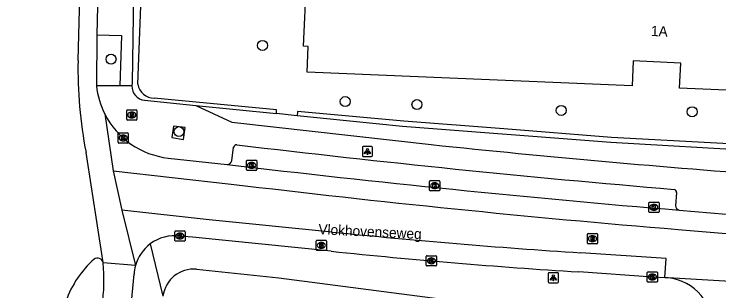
# Model space of a CAD drawing. Extents: x 161355 to 162026, y 386504 to 387459.
# Drawn here: x 161381.9 to 161450.8, y 386816.9 to 386843.9 of the extents above; entities that cross this region are included whole.
import ezdxf

# ---------------------------------------------------------------- set-up
doc = ezdxf.new("R2010")
doc.units = 0
for name, color, linetype in [('IMGEO_Boom', 7, 'Continuous'), ('IMGEO_Brandkraan', 7, 'Continuous'), ('IMGEO_Fietspad_gesloten', 7, 'Continuous'), ('IMGEO_Groenvoorziening', 7, 'Continuous'), ('IMGEO_Haag', 7, 'Continuous'), ('IMGEO_Kolk', 7, 'Continuous'), ('IMGEO_Lichtpunt', 7, 'Continuous'), ('IMGEO_Openbare_ruimte_label', 7, 'Continuous'), ('IMGEO_Pand', 7, 'Continuous'), ('IMGEO_Pand_nummerreeks', 7, 'Continuous'), ('IMGEO_Rijbaan_lokaal_gesloten', 7, 'Continuous'), ('IMGEO_Rijbaan_lokaal_open', 7, 'Continuous'), ('IMGEO_Rioolput', 7, 'Continuous'), ('IMGEO_Voetpad_open', 7, 'Continuous')]:
    doc.layers.add(name, color=color, linetype=linetype)

msp = doc.modelspace()

# ---------------------------------------------------------------- linework, layer by layer
at = {"layer": 'IMGEO_Boom'}
for centre in [(161406.16, 386840.885), (161391.344, 386839.543), (161414.259, 386835.401), (161421.273, 386835.11), (161435.387, 386834.536), (161448.192, 386834.404), (161397.993, 386832.461)]:
    msp.add_circle(centre, 0.489, dxfattribs=at)
at = {"layer": 'IMGEO_Brandkraan'}
for p, q in [((161392.882, 386833.669), (161392.882, 386834.521)), ((161392.957, 386834.595), (161393.809, 386834.595)), ((161393.37, 386834.375), (161393.395, 386834.375)), ((161393.883, 386834.521), (161393.883, 386833.669)), ((161393.809, 386833.595), (161392.957, 386833.595)), ((161393.393, 386833.815), (161393.368, 386833.815))]:
    msp.add_line(p, q, dxfattribs=at)
for points in [[(161392.882, 386833.669), (161392.882, 386834.521)], [(161392.957, 386834.595), (161393.809, 386834.595)], [(161393.23, 386834.295), (161393.23, 386833.895), (161393.443, 386833.895)], [(161393.461, 386834.295), (161393.23, 386834.295)], [(161393.883, 386834.521), (161393.883, 386833.669)], [(161393.809, 386833.595), (161392.957, 386833.595)], [(161393.409, 386834.214), (161393.355, 386834.214), (161393.355, 386834.138)], [(161393.355, 386834.138), (161393.408, 386834.138)], [(161393.417, 386834.062), (161393.355, 386834.062), (161393.355, 386833.981)], [(161393.355, 386833.981), (161393.417, 386833.981)]]:
    msp.add_lwpolyline(points, dxfattribs=at)
for centre, radius, start, end in [((161392.959, 386834.519), 0.0765, 91.55205, 178.44795), ((161392.959, 386834.519), 0.0765, 91.55205, 178.44795), ((161393.465, 386834.15), 0.145, 59.4692, 91.53667), ((161393.49, 386834.197), 0.0922, 285.51372, 58.15012), ((161393.807, 386834.519), 0.0765, 1.55205, 88.44795), ((161393.807, 386834.519), 0.0765, 1.55205, 88.44795), ((161392.959, 386833.671), 0.0765, 181.55205, 268.44795), ((161392.959, 386833.671), 0.0765, 181.55205, 268.44795), ((161393.41, 386834.176), 0.0379, 267.82845, 90.93552), ((161393.418, 386834.021), 0.0404, 269.87594, 90.50774), ((161393.449, 386834.146), 0.251, 268.66757, 293.53466), ((161393.495, 386834.005), 0.105, 301.31148, 78.98903), ((161393.807, 386833.671), 0.0765, 271.55205, 358.44795), ((161393.807, 386833.671), 0.0765, 271.55205, 358.44795)]:
    msp.add_arc(centre, radius, start, end, dxfattribs=at)
for centre, major_axis, ratio, start_param, end_param in [((161393.369, 386834.095), (-0.387, 0.002), 0.722429, 4.712389, 7.853982), ((161393.394, 386834.095), (-0.39, 0.002), 0.717154, 1.570796, 4.712389)]:
    msp.add_ellipse(centre, major_axis=major_axis, ratio=ratio, start_param=start_param, end_param=end_param, dxfattribs=at)
at = {"layer": 'IMGEO_Fietspad_gesloten'}
msp.add_lwpolyline([(161381.864, 386712.557), (161383.032, 386721.496), (161385.721, 386742.066), (161386.605, 386750), (161389.646, 386777.28), (161393.272, 386815.123), (161393.6, 386818.527)], dxfattribs=at)
for centre, radius, start, end in [((161373.711, 386817.975), 16.944, 351.43496, 5.63796), ((161397.624, 386818.31), 4.029, 164.69671, 176.90621)]:
    msp.add_arc(centre, radius, start, end, dxfattribs=at)
at = {"layer": 'IMGEO_Groenvoorziening'}
msp.add_lwpolyline([(161409.554, 386834.019), (161407.52, 386834.224)], dxfattribs=at)
at = {"layer": 'IMGEO_Haag'}
for points in [[(161393.965, 386837.094), (161395.556, 386878.648), (161396.501, 386879.764), (161425.128, 386878.71), (161433.124, 386871.146)], [(161407.52, 386834.224), (161407.534, 386834.586), (161395.561, 386835.719)], [(161399.64, 386835.019), (161407.52, 386834.224)], [(161481.019, 386829.466), (161481.006, 386830.048), (161455.439, 386831.092), (161440.307, 386831.903), (161429.776, 386832.736), (161419.975, 386833.49), (161409.586, 386834.431), (161409.554, 386834.019)], [(161481.019, 386829.466), (161454.814, 386830.559), (161440.24, 386831.401), (161419.848, 386832.981), (161409.554, 386834.019)]]:
    msp.add_lwpolyline(points, dxfattribs=at)
msp.add_arc((161395.593, 386837.37), 1.652, 189.63359, 268.87471, dxfattribs=at)
at = {"layer": 'IMGEO_Kolk'}
for p, q in [((161392.036, 386831.424), (161392.036, 386832.276)), ((161392.111, 386832.35), (161392.963, 386832.35)), ((161393.037, 386832.276), (161393.037, 386831.424)), ((161392.547, 386831.57), (161392.522, 386831.57)), ((161392.524, 386832.13), (161392.549, 386832.13)), ((161392.963, 386831.35), (161392.111, 386831.35)), ((161404.595, 386828.754), (161404.595, 386829.606)), ((161404.67, 386829.68), (161405.522, 386829.68)), ((161405.083, 386829.46), (161405.108, 386829.46)), ((161405.596, 386829.606), (161405.596, 386828.754)), ((161405.106, 386828.9), (161405.081, 386828.9)), ((161405.522, 386828.68), (161404.67, 386828.68)), ((161422.508, 386826.752), (161422.508, 386827.604)), ((161422.583, 386827.678), (161423.435, 386827.678)), ((161422.996, 386827.458), (161423.021, 386827.458)), ((161423.509, 386827.604), (161423.509, 386826.752)), ((161423.019, 386826.898), (161422.994, 386826.898)), ((161423.435, 386826.678), (161422.583, 386826.678)), ((161443.947, 386824.643), (161443.947, 386825.495)), ((161444.022, 386825.569), (161444.874, 386825.569)), ((161444.435, 386825.349), (161444.46, 386825.349)), ((161444.948, 386825.495), (161444.948, 386824.643)), ((161444.458, 386824.789), (161444.433, 386824.789)), ((161444.874, 386824.569), (161444.022, 386824.569)), ((161397.586, 386821.838), (161397.586, 386822.69)), ((161397.661, 386822.764), (161398.513, 386822.764)), ((161398.587, 386822.69), (161398.587, 386821.838)), ((161398.097, 386821.984), (161398.072, 386821.984)), ((161398.074, 386822.544), (161398.099, 386822.544)), ((161398.513, 386821.764), (161397.661, 386821.764)), ((161422.181, 386819.415), (161422.181, 386820.267)), ((161422.256, 386820.341), (161423.108, 386820.341)), ((161422.669, 386820.121), (161422.694, 386820.121)), ((161423.182, 386820.267), (161423.182, 386819.415)), ((161423.108, 386819.341), (161422.256, 386819.341)), ((161422.692, 386819.561), (161422.667, 386819.561)), ((161443.801, 386817.836), (161443.801, 386818.688)), ((161443.876, 386818.762), (161444.728, 386818.762)), ((161444.289, 386818.542), (161444.314, 386818.542)), ((161444.802, 386818.688), (161444.802, 386817.836)), ((161444.728, 386817.762), (161443.876, 386817.762)), ((161444.312, 386817.982), (161444.287, 386817.982))]:
    msp.add_line(p, q, dxfattribs=at)
for points in [[(161392.036, 386831.424), (161392.036, 386832.276)], [(161392.111, 386832.35), (161392.963, 386832.35)], [(161393.037, 386832.276), (161393.037, 386831.424)], [(161392.357, 386832.05), (161392.48, 386832.05), (161392.48, 386831.899), (161392.61, 386832.05), (161392.774, 386832.05), (161392.628, 386831.899), (161392.781, 386831.65), (161392.629, 386831.65), (161392.544, 386831.814), (161392.48, 386831.747), (161392.48, 386831.65), (161392.357, 386831.65), (161392.357, 386832.05)], [(161392.963, 386831.35), (161392.111, 386831.35)], [(161404.595, 386828.754), (161404.595, 386829.606)], [(161404.67, 386829.68), (161405.522, 386829.68)], [(161405.596, 386829.606), (161405.596, 386828.754)], [(161404.916, 386829.38), (161405.039, 386829.38), (161405.039, 386829.229), (161405.169, 386829.38), (161405.333, 386829.38), (161405.187, 386829.229), (161405.34, 386828.98), (161405.188, 386828.98), (161405.103, 386829.144), (161405.039, 386829.077), (161405.039, 386828.98), (161404.916, 386828.98), (161404.916, 386829.38)], [(161405.522, 386828.68), (161404.67, 386828.68)], [(161422.508, 386826.752), (161422.508, 386827.604)], [(161422.583, 386827.678), (161423.435, 386827.678)], [(161422.829, 386827.378), (161422.952, 386827.378), (161422.952, 386827.227), (161423.082, 386827.378), (161423.246, 386827.378), (161423.1, 386827.227), (161423.253, 386826.978), (161423.101, 386826.978), (161423.016, 386827.142), (161422.952, 386827.075), (161422.952, 386826.978), (161422.829, 386826.978), (161422.829, 386827.378)], [(161423.509, 386827.604), (161423.509, 386826.752)], [(161423.435, 386826.678), (161422.583, 386826.678)], [(161443.947, 386824.643), (161443.947, 386825.495)], [(161444.022, 386825.569), (161444.874, 386825.569)], [(161444.948, 386825.495), (161444.948, 386824.643)], [(161444.268, 386825.269), (161444.391, 386825.269), (161444.391, 386825.118), (161444.521, 386825.269), (161444.685, 386825.269), (161444.539, 386825.118), (161444.692, 386824.869), (161444.54, 386824.869), (161444.455, 386825.033), (161444.391, 386824.966), (161444.391, 386824.869), (161444.268, 386824.869), (161444.268, 386825.269)], [(161444.874, 386824.569), (161444.022, 386824.569)], [(161397.586, 386821.838), (161397.586, 386822.69)], [(161397.661, 386822.764), (161398.513, 386822.764)], [(161398.587, 386822.69), (161398.587, 386821.838)], [(161397.907, 386822.464), (161398.03, 386822.464), (161398.03, 386822.313), (161398.16, 386822.464), (161398.324, 386822.464), (161398.178, 386822.313), (161398.331, 386822.064), (161398.179, 386822.064), (161398.094, 386822.228), (161398.03, 386822.161), (161398.03, 386822.064), (161397.907, 386822.064), (161397.907, 386822.464)], [(161398.513, 386821.764), (161397.661, 386821.764)], [(161422.181, 386819.415), (161422.181, 386820.267)], [(161422.256, 386820.341), (161423.108, 386820.341)], [(161422.502, 386820.041), (161422.625, 386820.041), (161422.625, 386819.89), (161422.755, 386820.041), (161422.919, 386820.041), (161422.773, 386819.89), (161422.926, 386819.641), (161422.774, 386819.641), (161422.689, 386819.805), (161422.625, 386819.738), (161422.625, 386819.641), (161422.502, 386819.641), (161422.502, 386820.041)], [(161423.182, 386820.267), (161423.182, 386819.415)], [(161423.108, 386819.341), (161422.256, 386819.341)], [(161443.801, 386817.836), (161443.801, 386818.688)], [(161443.876, 386818.762), (161444.728, 386818.762)], [(161444.122, 386818.462), (161444.245, 386818.462), (161444.245, 386818.311), (161444.375, 386818.462), (161444.539, 386818.462), (161444.393, 386818.311), (161444.546, 386818.062), (161444.394, 386818.062), (161444.309, 386818.226), (161444.245, 386818.159), (161444.245, 386818.062), (161444.122, 386818.062), (161444.122, 386818.462)], [(161444.802, 386818.688), (161444.802, 386817.836)], [(161444.728, 386817.762), (161443.876, 386817.762)]]:
    msp.add_lwpolyline(points, dxfattribs=at)
for centre, start, end in [((161392.113, 386832.274), 91.55205, 178.44795), ((161392.113, 386832.274), 91.55205, 178.44795), ((161392.961, 386832.274), 1.55205, 88.44795), ((161392.961, 386832.274), 1.55205, 88.44795), ((161392.113, 386831.426), 181.55205, 268.44795), ((161392.113, 386831.426), 181.55205, 268.44795), ((161392.961, 386831.426), 271.55205, 358.44795), ((161392.961, 386831.426), 271.55205, 358.44795), ((161404.672, 386829.604), 91.55205, 178.44795), ((161404.672, 386829.604), 91.55205, 178.44795), ((161405.52, 386829.604), 1.55205, 88.44795), ((161405.52, 386829.604), 1.55205, 88.44795), ((161404.672, 386828.756), 181.55205, 268.44795), ((161404.672, 386828.756), 181.55205, 268.44795), ((161405.52, 386828.756), 271.55205, 358.44795), ((161405.52, 386828.756), 271.55205, 358.44795), ((161422.585, 386827.602), 91.55205, 178.44795), ((161422.585, 386827.602), 91.55205, 178.44795), ((161423.433, 386827.602), 1.55205, 88.44795), ((161423.433, 386827.602), 1.55205, 88.44795), ((161422.585, 386826.754), 181.55205, 268.44795), ((161422.585, 386826.754), 181.55205, 268.44795), ((161423.433, 386826.754), 271.55205, 358.44795), ((161423.433, 386826.754), 271.55205, 358.44795), ((161444.024, 386825.493), 91.55205, 178.44795), ((161444.024, 386825.493), 91.55205, 178.44795), ((161444.872, 386825.493), 1.55205, 88.44795), ((161444.872, 386825.493), 1.55205, 88.44795), ((161444.024, 386824.645), 181.55205, 268.44795), ((161444.024, 386824.645), 181.55205, 268.44795), ((161444.872, 386824.645), 271.55205, 358.44795), ((161444.872, 386824.645), 271.55205, 358.44795), ((161397.663, 386822.688), 91.55205, 178.44795), ((161397.663, 386822.688), 91.55205, 178.44795), ((161398.511, 386822.688), 1.55205, 88.44795), ((161398.511, 386822.688), 1.55205, 88.44795), ((161397.663, 386821.84), 181.55205, 268.44795), ((161397.663, 386821.84), 181.55205, 268.44795), ((161398.511, 386821.84), 271.55205, 358.44795), ((161398.511, 386821.84), 271.55205, 358.44795), ((161422.258, 386820.265), 91.55205, 178.44795), ((161422.258, 386820.265), 91.55205, 178.44795), ((161423.106, 386820.265), 1.55205, 88.44795), ((161423.106, 386820.265), 1.55205, 88.44795), ((161422.258, 386819.417), 181.55205, 268.44795), ((161422.258, 386819.417), 181.55205, 268.44795), ((161423.106, 386819.417), 271.55205, 358.44795), ((161423.106, 386819.417), 271.55205, 358.44795), ((161443.878, 386818.686), 91.55205, 178.44795), ((161443.878, 386818.686), 91.55205, 178.44795), ((161444.726, 386818.686), 1.55205, 88.44795), ((161444.726, 386818.686), 1.55205, 88.44795), ((161443.878, 386817.838), 181.55205, 268.44795), ((161443.878, 386817.838), 181.55205, 268.44795), ((161444.726, 386817.838), 271.55205, 358.44795), ((161444.726, 386817.838), 271.55205, 358.44795)]:
    msp.add_arc(centre, 0.0765, start, end, dxfattribs=at)
for centre, major_axis, ratio, start_param, end_param in [((161392.523, 386831.85), (-0.387, 0.002), 0.722429, 4.712389, 7.853982), ((161392.548, 386831.85), (-0.39, 0.002), 0.717154, 1.570796, 4.712389), ((161405.082, 386829.18), (-0.387, 0.002), 0.722429, 4.712389, 7.853982), ((161405.107, 386829.18), (-0.39, 0.002), 0.717154, 1.570796, 4.712389), ((161422.995, 386827.178), (-0.387, 0.002), 0.722429, 4.712389, 7.853982), ((161423.02, 386827.178), (-0.39, 0.002), 0.717154, 1.570796, 4.712389), ((161444.434, 386825.069), (-0.387, 0.002), 0.722429, 4.712389, 7.853982), ((161444.459, 386825.069), (-0.39, 0.002), 0.717154, 1.570796, 4.712389), ((161398.073, 386822.264), (-0.387, 0.002), 0.722429, 4.712389, 7.853982), ((161398.098, 386822.264), (-0.39, 0.002), 0.717154, 1.570796, 4.712389), ((161422.668, 386819.841), (-0.387, 0.002), 0.722429, 4.712389, 7.853982), ((161422.693, 386819.841), (-0.39, 0.002), 0.717154, 1.570796, 4.712389), ((161444.288, 386818.262), (-0.387, 0.002), 0.722429, 4.712389, 7.853982), ((161444.313, 386818.262), (-0.39, 0.002), 0.717154, 1.570796, 4.712389)]:
    msp.add_ellipse(centre, major_axis=major_axis, ratio=ratio, start_param=start_param, end_param=end_param, dxfattribs=at)
at = {"layer": 'IMGEO_Lichtpunt'}
for p, q in [((161415.929, 386830.927), (161415.929, 386830.12)), ((161415.929, 386830.927), (161415.929, 386830.12)), ((161416.831, 386831.022), (161416.023, 386831.022)), ((161416.831, 386831.022), (161416.023, 386831.022)), ((161416.925, 386830.12), (161416.925, 386830.927)), ((161416.925, 386830.12), (161416.925, 386830.927)), ((161416.023, 386830.026), (161416.831, 386830.026)), ((161416.023, 386830.026), (161416.831, 386830.026)), ((161434.115, 386818.588), (161434.115, 386817.781)), ((161434.115, 386818.588), (161434.115, 386817.781)), ((161435.017, 386818.683), (161434.209, 386818.683)), ((161435.017, 386818.683), (161434.209, 386818.683)), ((161435.111, 386817.781), (161435.111, 386818.588)), ((161435.111, 386817.781), (161435.111, 386818.588)), ((161434.209, 386817.687), (161435.017, 386817.687)), ((161434.209, 386817.687), (161435.017, 386817.687))]:
    msp.add_line(p, q, dxfattribs=at)
for points in [[(161416.303, 386830.591), (161416.342, 386830.563), (161416.154, 386830.301), (161416.116, 386830.328), (161416.303, 386830.591)], [(161416.405, 386830.543), (161416.452, 386830.543), (161416.452, 386830.221), (161416.405, 386830.221), (161416.405, 386830.543)], [(161416.515, 386830.563), (161416.553, 386830.59), (161416.74, 386830.328), (161416.701, 386830.3), (161416.515, 386830.563)], [(161434.489, 386818.252), (161434.528, 386818.224), (161434.34, 386817.962), (161434.302, 386817.989), (161434.489, 386818.252)], [(161434.591, 386818.204), (161434.638, 386818.204), (161434.638, 386817.882), (161434.591, 386817.882), (161434.591, 386818.204)], [(161434.701, 386818.224), (161434.739, 386818.251), (161434.926, 386817.989), (161434.887, 386817.961), (161434.701, 386818.224)]]:
    msp.add_lwpolyline(points, dxfattribs=at)
for centre in [(161416.428, 386830.725), (161434.614, 386818.386)]:
    msp.add_circle(centre, 0.0994, dxfattribs=at)
for centre, start, end in [((161416.023, 386830.927), 90, 180), ((161416.023, 386830.927), 90, 180), ((161416.831, 386830.927), 0, 90), ((161416.831, 386830.927), 0, 90), ((161416.023, 386830.12), 180, 270), ((161416.023, 386830.12), 180, 270), ((161416.831, 386830.12), 270, 0), ((161416.831, 386830.12), 270, 360), ((161434.209, 386818.588), 90, 180), ((161434.209, 386818.588), 90, 180), ((161435.017, 386818.588), 0, 90), ((161435.017, 386818.588), 0, 90), ((161434.209, 386817.781), 180, 270), ((161434.209, 386817.781), 180, 270), ((161435.017, 386817.781), 270, 0), ((161435.017, 386817.781), 270, 360)]:
    msp.add_arc(centre, 0.0946, start, end, dxfattribs=at)
at = {"layer": 'IMGEO_Pand'}
msp.add_lwpolyline([(161472.915, 386835.593), (161446.965, 386836.705), (161447.071, 386839.165), (161442.426, 386839.364), (161442.322, 386836.926), (161410.53, 386838.288), (161410.637, 386840.778), (161410.178, 386840.797), (161410.451, 386847.174), (161411.011, 386847.15), (161411.114, 386849.55), (161414.702, 386849.396), (161415.023, 386856.882), (161407.942, 386857.185), (161408.051, 386859.721), (161404.592, 386859.869), (161404.693, 386862.235), (161404.167, 386862.258), (161404.443, 386868.709), (161404.931, 386868.688), (161405.032, 386871.045), (161433.093, 386869.843)], dxfattribs=at)
at = {"layer": 'IMGEO_Rijbaan_lokaal_gesloten'}
for points in [[(161388.119, 386839.423), (161388.746, 386863.053), (161388.763, 386863.237), (161389.344, 386874.852), (161394.233, 386932.401), (161402.616, 387030.052), (161406.674, 387079.565)], [(161393.276, 386900.594), (161392.131, 386887.36), (161391.553, 386880.481), (161391.006, 386873.978), (161390.834, 386871.554), (161390.584, 386865.228), (161390.456, 386862.885), (161390.188, 386851.816), (161389.96, 386841.92)], [(161389.96, 386841.92), (161389.919, 386836.924)], [(161390.735, 386834.187), (161391.564, 386828.627)], [(161390.573, 386819.64), (161390.571, 386819.676), (161388.899, 386830.426)], [(161396.95, 386829.882), (161402.712, 386829.261)], [(161391.564, 386828.627), (161403.087, 386827.345)], [(161391.564, 386828.627), (161392.402, 386824.783)], [(161392.402, 386824.783), (161393.737, 386819.373)], [(161412.991, 386822.658), (161400.945, 386823.863), (161392.402, 386824.783)], [(161446.92, 386824.791), (161451.508, 386824.408)], [(161446.82, 386822.904), (161451.897, 386822.494)], [(161412.876, 386820.776), (161399.307, 386822.14), (161398.087, 386822.264)], [(161445.522, 386818.195), (161445.646, 386820.07), (161437.303, 386820.631)], [(161393.737, 386819.373), (161390.573, 386819.64)], [(161445.522, 386818.195), (161444.302, 386818.262), (161437.112, 386818.754)]]:
    msp.add_lwpolyline(points, dxfattribs=at)
for centre, radius, start, end in [((161430.948, 386838.604), 42.837, 178.90424, 191.00556), ((161397.824, 386837.791), 7.953, 186.25703, 206.94547), ((161397.835, 386837.798), 7.966, 206.96008, 263.62086), ((161549.773, 388062.844), 1242.318, 263.201589, 265.25097), ((161544.782, 388005.138), 1186.286, 263.139992, 265.263214), ((161479.745, 387476.502), 657.243, 264.170569, 266.297467), ((161397.577, 386818.31), 3.987, 82.64494, 126.88105), ((161397.6, 386818.299), 4.01, 127.05636, 164.4636), ((161475.855, 387429.389), 611.863, 264.092114, 266.369646), ((161396.22, 386812.667), 9.827, 131.69474, 160.71213), ((161390.016, 386819.549), 0.565, 9.28592, 126.1158)]:
    msp.add_arc(centre, radius, start, end, dxfattribs=at)
at = {"layer": 'IMGEO_Rijbaan_lokaal_open'}
for points in [[(161445.845, 386818.176), (161445.522, 386818.195)], [(161460.843, 386817.301), (161445.845, 386818.176)]]:
    msp.add_lwpolyline(points, dxfattribs=at)
msp.add_arc((161445.409, 386813.48), 4.716, 353.41201, 84.69576, dxfattribs=at)
at = {"layer": 'IMGEO_Rioolput'}
for p, q in [((161437.939, 386821.581), (161437.939, 386822.433)), ((161438.014, 386822.507), (161438.866, 386822.507)), ((161438.427, 386822.287), (161438.452, 386822.287)), ((161438.94, 386822.433), (161438.94, 386821.581)), ((161411.417, 386820.924), (161411.417, 386821.776)), ((161411.492, 386821.85), (161412.344, 386821.85)), ((161411.905, 386821.63), (161411.93, 386821.63)), ((161412.418, 386821.776), (161412.418, 386820.924)), ((161438.866, 386821.507), (161438.014, 386821.507)), ((161438.45, 386821.727), (161438.425, 386821.727)), ((161412.344, 386820.85), (161411.492, 386820.85)), ((161411.928, 386821.07), (161411.903, 386821.07))]:
    msp.add_line(p, q, dxfattribs=at)
for points in [[(161437.939, 386821.581), (161437.939, 386822.433)], [(161438.014, 386822.507), (161438.866, 386822.507)], [(161438.528, 386822.205), (161438.276, 386822.207), (161438.276, 386821.807)], [(161438.276, 386821.807), (161438.4, 386821.807), (161438.4, 386821.969), (161438.411, 386821.969)], [(161438.454, 386822.126), (161438.4, 386822.126), (161438.4, 386822.045)], [(161438.4, 386822.045), (161438.452, 386822.045)], [(161438.458, 386821.94), (161438.529, 386821.807), (161438.669, 386821.807), (161438.604, 386821.933)], [(161438.94, 386822.433), (161438.94, 386821.581)], [(161411.417, 386820.924), (161411.417, 386821.776)], [(161411.492, 386821.85), (161412.344, 386821.85)], [(161412.006, 386821.548), (161411.754, 386821.55), (161411.754, 386821.15)], [(161411.754, 386821.15), (161411.878, 386821.15), (161411.878, 386821.312), (161411.889, 386821.312)], [(161411.932, 386821.469), (161411.878, 386821.469), (161411.878, 386821.388)], [(161411.878, 386821.388), (161411.93, 386821.388)], [(161411.936, 386821.283), (161412.007, 386821.15), (161412.147, 386821.15), (161412.082, 386821.276)], [(161412.418, 386821.776), (161412.418, 386820.924)], [(161438.866, 386821.507), (161438.014, 386821.507)], [(161412.344, 386820.85), (161411.492, 386820.85)]]:
    msp.add_lwpolyline(points, dxfattribs=at)
for centre, radius, start, end in [((161438.016, 386822.431), 0.0765, 91.55205, 178.44795), ((161438.016, 386822.431), 0.0765, 91.55205, 178.44795), ((161438.41, 386821.916), 0.0533, 26.02933, 88.69889), ((161438.436, 386822.234), 0.19, 274.7715, 282.96867), ((161438.46, 386822.03), 0.0964, 77.00612, 93.18647), ((161438.474, 386822.087), 0.0378, 276.66336, 79.67722), ((161438.527, 386822.095), 0.109, 350.36119, 89.41601), ((161438.525, 386822.095), 0.112, 277.58423, 350.98172), ((161438.509, 386821.88), 0.108, 29.51342, 73.79051), ((161438.864, 386822.431), 0.0765, 1.55205, 88.44795), ((161438.864, 386822.431), 0.0765, 1.55205, 88.44795), ((161411.494, 386821.774), 0.0765, 91.55205, 178.44795), ((161411.494, 386821.774), 0.0765, 91.55205, 178.44795), ((161411.888, 386821.259), 0.0533, 26.02933, 88.69889), ((161411.914, 386821.577), 0.19, 274.7715, 282.96867), ((161411.938, 386821.373), 0.0964, 77.00612, 93.18647), ((161411.952, 386821.43), 0.0378, 276.66336, 79.67722), ((161412.005, 386821.438), 0.109, 350.36119, 89.41601), ((161412.003, 386821.438), 0.112, 277.58423, 350.98172), ((161411.987, 386821.223), 0.108, 29.51342, 73.79051), ((161412.342, 386821.774), 0.0765, 1.55205, 88.44795), ((161412.342, 386821.774), 0.0765, 1.55205, 88.44795), ((161438.016, 386821.583), 0.0765, 181.55205, 268.44795), ((161438.016, 386821.583), 0.0765, 181.55205, 268.44795), ((161438.864, 386821.583), 0.0765, 271.55205, 358.44795), ((161438.864, 386821.583), 0.0765, 271.55205, 358.44795), ((161411.494, 386820.926), 0.0765, 181.55205, 268.44795), ((161411.494, 386820.926), 0.0765, 181.55205, 268.44795), ((161412.342, 386820.926), 0.0765, 271.55205, 358.44795), ((161412.342, 386820.926), 0.0765, 271.55205, 358.44795)]:
    msp.add_arc(centre, radius, start, end, dxfattribs=at)
for centre, major_axis, ratio, start_param, end_param in [((161438.426, 386822.007), (-0.387, 0.002), 0.722429, 4.712389, 7.853982), ((161438.451, 386822.007), (-0.39, 0.002), 0.717154, 1.570796, 4.712389), ((161411.904, 386821.35), (-0.387, 0.002), 0.722429, 4.712389, 7.853982), ((161411.929, 386821.35), (-0.39, 0.002), 0.717154, 1.570796, 4.712389)]:
    msp.add_ellipse(centre, major_axis=major_axis, ratio=ratio, start_param=start_param, end_param=end_param, dxfattribs=at)
at = {"layer": 'IMGEO_Voetpad_open'}
for points in [[(161394.85, 386877.871), (161393.744, 386859.202), (161393.698, 386856.855), (161393.408, 386837.221), (161393.397, 386836.946)], [(161389.96, 386841.92), (161392.357, 386841.864), (161392.218, 386836.939)], [(161392.218, 386836.939), (161389.919, 386836.924)], [(161393.397, 386836.946), (161392.218, 386836.939)], [(161394.634, 386835.524), (161399.64, 386835.019)], [(161399.64, 386835.019), (161403.163, 386833.375), (161422.665, 386831.199)], [(161398.423, 386831.703), (161398.591, 386832.852), (161397.443, 386833.007), (161397.29, 386831.893), (161398.423, 386831.703)], [(161403.166, 386829.62), (161403.327, 386830.956)], [(161446.668, 386826.522), (161446.576, 386825.226)], [(161395.184, 386821.499), (161396.429, 386816.391)], [(161399.71, 386819.014), (161407.753, 386818.166), (161426.814, 386815.709)]]:
    msp.add_lwpolyline(points, dxfattribs=at)
for centre, radius, start, end in [((161394.772, 386836.893), 1.376, 177.81226, 264.22785), ((161403.662, 386830.815), 0.364, 90.36814, 157.2499), ((161546.535, 388022.74), 1200.096, 263.162538, 265.215244), ((161544.758, 388001.915), 1177.065, 264.046191, 265.713659), ((161402.718, 386829.72), 0.459, 269.27137, 347.39893), ((161446.332, 386826.505), 0.336, 2.87876, 72.76675), ((161447.002, 386825.209), 0.426, 177.76487, 258.90935), ((161399.424, 386816.008), 3.02, 84.56742, 172.71385)]:
    msp.add_arc(centre, radius, start, end, dxfattribs=at)

# ---------------------------------------------------------------- texts
at = {"layer": 'IMGEO_Openbare_ruimte_label'}
msp.add_text('Vlokhovenseweg', height=1, rotation=357.30639, dxfattribs=at).set_placement((161411.612, 386822.438))
at = {"layer": 'IMGEO_Pand_nummerreeks'}
msp.add_text('1A', height=1, rotation=357.54684, dxfattribs=at).set_placement((161444.144, 386841.812))

doc.saveas('drawing.dxf')
